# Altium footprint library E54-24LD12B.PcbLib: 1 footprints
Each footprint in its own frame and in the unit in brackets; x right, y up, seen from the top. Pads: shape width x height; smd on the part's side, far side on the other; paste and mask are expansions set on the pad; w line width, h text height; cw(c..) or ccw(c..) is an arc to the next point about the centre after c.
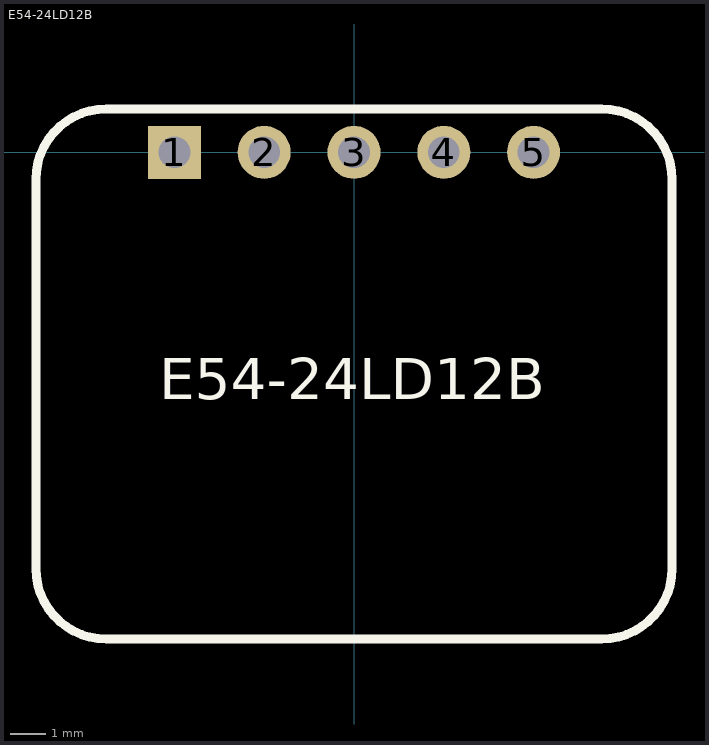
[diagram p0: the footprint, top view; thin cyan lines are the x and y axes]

## E54-24LD12B [mm]
pads (5):
  rect 1.5x1.5 hole 0.9 paste-2539.97 mask+0: 1(-5.08,0)
  round 1.5 hole 0.9 paste-2539.97 mask+0: 2(-2.54,0) 3(0,0) 4(2.54,0) 5(5.08,0)
Top Overlay:
  lines w0.254: -9,-11.77 ccw(c-7,-11.77) -7,-13.77 7,-13.77 ccw(c7,-11.77) 9,-11.77 9,-0.77 ccw(c7,-0.77) 7,1.23 -7,1.23 ccw(c-7,-0.77) -9,-0.77 -9,-11.77
  text "E54-24LD12B" at -5.508,-7.363 h2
